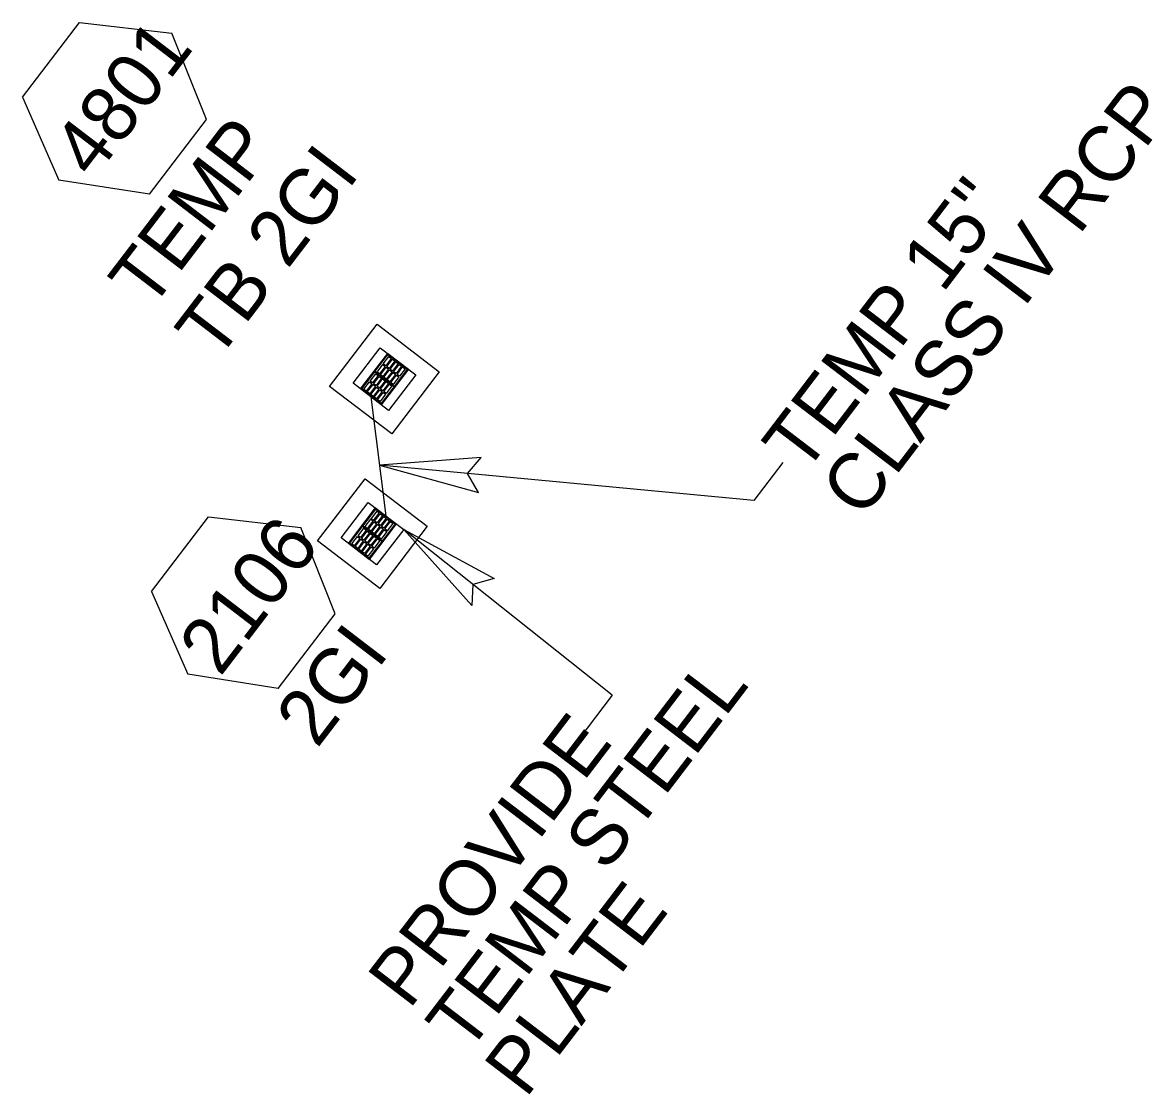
# Model space of a CAD drawing. Extents: x 2214419 to 2238519, y 983271 to 1015868.
# Drawn here: x 2224968.5 to 2225069.6, y 994806.5 to 994902.4 of the extents above; entities that cross this region are included whole.
import ezdxf

# ---------------------------------------------------------------- set-up
doc = ezdxf.new("R2010")
doc.units = 0
for name, color, linetype in [('Prop Drainage Structure Box Number Symbol CELL', 7, 'Continuous'), ('Prop Drainage Structure Drop Inlet Grate 2 Wide Slots and Sag Grates 840 22 CELL', 7, 'Continuous'), ('Prop Drainage Structure Drop Inlet Grate 2 Wide Slots and Sag Grates 840 22 Label', 7, 'Continuous'), ('Prop Drainage Structure Drop Inlet Grate 2 Wide Slots and Sag Grates 840 22 TB CELL', 7, 'Continuous'), ('Prop Drainage Structure Drop Inlet Grate 2 Wide Slots and Sag Grates 840 22 TB Label', 7, 'Continuous'), ('Prop Drainage Structure Pipe Alternate 15in', 7, 'Continuous'), ('Prop Drainage Structure Plot Symbol 20 Scale', 7, 'Continuous'), ('Prop Drainage Structure Plot Symbol 50 Scale', 7, 'Continuous'), ('Prop Plan Preparation Drainage Notes Label', 7, 'Continuous')]:
    doc.layers.add(name, color=color, linetype=linetype)

msp = doc.modelspace()

# ---------------------------------------------------------------- linework, layer by layer
at = {"layer": 'Prop Drainage Structure Box Number Symbol CELL'}
for p, q in [((2224968.47, 994895.68), (2224973.57, 994902.35)), ((2224973.57, 994902.35), (2224981.83, 994901.41)), ((2224984.91, 994893.68), (2224981.83, 994901.41)), ((2224968.47, 994895.68), (2224971.71, 994888.27)), ((2224979.81, 994887.01), (2224984.91, 994893.68)), ((2224979.81, 994887.01), (2224971.71, 994888.27)), ((2224980.01, 994851.47), (2224985.11, 994858.14)), ((2224985.11, 994858.14), (2224993.37, 994857.2)), ((2224996.45, 994849.47), (2224993.37, 994857.2)), ((2224980.01, 994851.47), (2224983.24, 994844.07)), ((2224991.35, 994842.8), (2224996.45, 994849.47)), ((2224991.35, 994842.8), (2224983.24, 994844.07))]:
    msp.add_line(p, q, dxfattribs=at)
at = {"layer": 'Prop Drainage Structure Drop Inlet Grate 2 Wide Slots and Sag Grates 840 22 CELL'}
for p, q in [((2225000.98, 994858.23), (2225000.98, 994858.23)), ((2224998.84, 994857.35), (2224998.84, 994857.35)), ((2224999.76, 994856.64), (2224999.76, 994856.64)), ((2225000.69, 994855.93), (2225000.69, 994855.93)), ((2224998.55, 994855.05), (2224998.55, 994855.05))]:
    msp.add_line(p, q, dxfattribs=at)
for points in [[(2224997.62, 994855.76), (2225000.05, 994858.94), (2225001.9, 994857.52), (2224999.48, 994854.34), (2224997.62, 994855.76)], [(2224997.71, 994855.77), (2225000.06, 994858.85), (2225001.82, 994857.51), (2224999.46, 994854.43), (2224997.71, 994855.77)], [(2224998.9, 994857.31), (2225000.06, 994858.84), (2225001.8, 994857.51), (2225000.64, 994855.98), (2224998.9, 994857.31)], [(2224999.32, 994857.1), (2224999.82, 994857.76), (2224999.61, 994857.93), (2224999.1, 994857.27), (2224999.32, 994857.1)], [(2224999.87, 994857.83), (2225000.38, 994858.49), (2225000.16, 994858.66), (2224999.66, 994857.99), (2224999.87, 994857.83)], [(2224999.96, 994857.76), (2225000.47, 994858.42), (2225000.68, 994858.26), (2225000.18, 994857.6), (2224999.96, 994857.76)], [(2225000.27, 994857.53), (2225000.78, 994858.19), (2225000.99, 994858.02), (2225000.48, 994857.36), (2225000.27, 994857.53)], [(2225000.58, 994857.29), (2225001.08, 994857.95), (2225001.3, 994857.79), (2225000.79, 994857.13), (2225000.58, 994857.29)], [(2224997.72, 994855.77), (2224998.89, 994857.3), (2225000.63, 994855.97), (2224999.46, 994854.45), (2224997.72, 994855.77)], [(2224998.48, 994856.45), (2224998.99, 994857.12), (2224999.2, 994856.95), (2224998.7, 994856.29), (2224998.48, 994856.45)], [(2224998.79, 994856.22), (2224999.29, 994856.88), (2224999.51, 994856.72), (2224999, 994856.06), (2224998.79, 994856.22)], [(2224999.41, 994857.03), (2224999.91, 994857.69), (2225000.13, 994857.53), (2224999.62, 994856.87), (2224999.41, 994857.03)], [(2224999.71, 994856.8), (2225000.22, 994857.46), (2225000.43, 994857.3), (2224999.93, 994856.63), (2224999.71, 994856.8)], [(2225000.02, 994856.56), (2225000.53, 994857.23), (2225000.74, 994857.06), (2225000.23, 994856.4), (2225000.02, 994856.56)], [(2225000.33, 994856.33), (2225000.83, 994856.99), (2225001.05, 994856.83), (2225000.54, 994856.16), (2225000.33, 994856.33)], [(2225000.88, 994857.06), (2225001.39, 994857.72), (2225001.6, 994857.56), (2225001.1, 994856.89), (2225000.88, 994857.06)], [(2224997.92, 994855.73), (2224998.43, 994856.39), (2224998.65, 994856.22), (2224998.14, 994855.56), (2224997.92, 994855.73)], [(2224998.23, 994855.49), (2224998.74, 994856.15), (2224998.95, 994855.99), (2224998.45, 994855.33), (2224998.23, 994855.49)], [(2224998.54, 994855.26), (2224999.04, 994855.92), (2224999.26, 994855.76), (2224998.75, 994855.09), (2224998.54, 994855.26)], [(2224999.09, 994855.99), (2224999.6, 994856.65), (2224999.81, 994856.48), (2224999.31, 994855.82), (2224999.09, 994855.99)], [(2224999.4, 994855.75), (2224999.91, 994856.41), (2225000.12, 994856.25), (2224999.61, 994855.59), (2224999.4, 994855.75)], [(2224999.71, 994855.52), (2225000.21, 994856.18), (2225000.43, 994856.02), (2224999.92, 994855.35), (2224999.71, 994855.52)], [(2224998.84, 994855.02), (2224999.35, 994855.69), (2224999.56, 994855.52), (2224999.06, 994854.86), (2224998.84, 994855.02)], [(2224999.15, 994854.79), (2224999.65, 994855.45), (2224999.87, 994855.29), (2224999.36, 994854.63), (2224999.15, 994854.79)]]:
    msp.add_lwpolyline(points, dxfattribs=at)
at = {"layer": 'Prop Drainage Structure Drop Inlet Grate 2 Wide Slots and Sag Grates 840 22 TB CELL'}
for p, q in [((2225002.06, 994872.06), (2225002.06, 994872.06)), ((2224999.92, 994871.18), (2224999.92, 994871.18)), ((2225000.85, 994870.47), (2225000.85, 994870.47)), ((2225001.78, 994869.76), (2225001.78, 994869.76)), ((2224999.63, 994868.88), (2224999.63, 994868.88))]:
    msp.add_line(p, q, dxfattribs=at)
for points in [[(2225002.99, 994871.35), (2225000.56, 994868.17), (2224998.71, 994869.59), (2225001.14, 994872.77), (2225002.99, 994871.35)], [(2225002.9, 994871.34), (2225000.55, 994868.26), (2224998.79, 994869.6), (2225001.15, 994872.68), (2225002.9, 994871.34), (2225002.9, 994871.34)], [(2225002.89, 994871.34), (2225001.72, 994869.81), (2224999.99, 994871.14), (2225001.15, 994872.67), (2225002.89, 994871.34)], [(2225001.46, 994872.32), (2225000.96, 994871.66), (2225000.74, 994871.82), (2225001.25, 994872.49), (2225001.46, 994872.32)], [(2225001.77, 994872.09), (2225001.26, 994871.42), (2225001.05, 994871.59), (2225001.55, 994872.25), (2225001.77, 994872.09)], [(2225001.71, 994869.8), (2225000.55, 994868.27), (2224998.81, 994869.6), (2224999.97, 994871.13), (2225001.71, 994869.8)], [(2225000.91, 994871.59), (2225000.4, 994870.93), (2225000.19, 994871.09), (2225000.69, 994871.76), (2225000.91, 994871.59)], [(2225001.21, 994871.36), (2225000.71, 994870.7), (2225000.49, 994870.86), (2225001, 994871.52), (2225001.21, 994871.36)], [(2225001.52, 994871.12), (2225001.01, 994870.46), (2225000.8, 994870.63), (2225001.3, 994871.29), (2225001.52, 994871.12)], [(2225001.83, 994870.89), (2225001.32, 994870.23), (2225001.1, 994870.39), (2225001.61, 994871.05), (2225001.83, 994870.89)], [(2225002.08, 994871.85), (2225001.57, 994871.19), (2225001.35, 994871.35), (2225001.86, 994872.02), (2225002.08, 994871.85)], [(2225002.38, 994871.62), (2225001.88, 994870.96), (2225001.66, 994871.12), (2225002.17, 994871.78), (2225002.38, 994871.62)], [(2225002.69, 994871.38), (2225002.18, 994870.72), (2225001.97, 994870.89), (2225002.47, 994871.55), (2225002.69, 994871.38)], [(2224999.73, 994870.05), (2224999.22, 994869.39), (2224999.01, 994869.56), (2224999.51, 994870.22), (2224999.73, 994870.05)], [(2225000.29, 994870.78), (2224999.78, 994870.12), (2224999.57, 994870.28), (2225000.07, 994870.95), (2225000.29, 994870.78)], [(2225000.59, 994870.55), (2225000.09, 994869.89), (2224999.87, 994870.05), (2225000.38, 994870.71), (2225000.59, 994870.55)], [(2225000.9, 994870.31), (2225000.39, 994869.65), (2225000.18, 994869.82), (2225000.68, 994870.48), (2225000.9, 994870.31)], [(2225001.21, 994870.08), (2225000.7, 994869.42), (2225000.48, 994869.58), (2225000.99, 994870.24), (2225001.21, 994870.08)], [(2225002.13, 994870.66), (2225001.63, 994869.99), (2225001.41, 994870.16), (2225001.92, 994870.82), (2225002.13, 994870.66)], [(2225000.04, 994869.82), (2224999.53, 994869.16), (2224999.31, 994869.32), (2224999.82, 994869.98), (2225000.04, 994869.82)], [(2225000.34, 994869.58), (2224999.84, 994868.92), (2224999.62, 994869.09), (2225000.13, 994869.75), (2225000.34, 994869.58)], [(2225000.65, 994869.35), (2225000.14, 994868.69), (2224999.93, 994868.85), (2225000.43, 994869.52), (2225000.65, 994869.35)], [(2225000.95, 994869.12), (2225000.45, 994868.45), (2225000.23, 994868.62), (2225000.74, 994869.28), (2225000.95, 994869.12)], [(2225001.51, 994869.85), (2225001.01, 994869.18), (2225000.79, 994869.35), (2225001.3, 994870.01), (2225001.51, 994869.85)]]:
    msp.add_lwpolyline(points, dxfattribs=at)
at = {"layer": 'Prop Drainage Structure Pipe Alternate 15in'}
msp.add_line((2224999.63, 994868.88), (2225000.98, 994858.23), dxfattribs=at)
at = {"layer": 'Prop Drainage Structure Plot Symbol 20 Scale'}
for points in [[(2225003.65, 994870.84), (2225001.22, 994867.67), (2224998.04, 994870.1), (2225000.47, 994873.27)], [(2224996.96, 994856.27), (2224999.39, 994859.44), (2225002.57, 994857.02), (2225000.14, 994853.84)]]:
    msp.add_lwpolyline(points, close=True, dxfattribs=at)
at = {"layer": 'Prop Drainage Structure Plot Symbol 50 Scale'}
for points in [[(2225005.75, 994871.13), (2225001.5, 994865.56), (2224995.94, 994869.81), (2225000.19, 994875.38)], [(2224994.86, 994855.99), (2224999.11, 994861.55), (2225004.67, 994857.3), (2225000.42, 994851.73)]]:
    msp.add_lwpolyline(points, close=True, dxfattribs=at)
at = {"layer": 'Prop Plan Preparation Drainage Notes Label'}
for p, q in [((2225036.49, 994863.01), (2225033.88, 994859.6)), ((2225033.88, 994859.6), (2225000.41, 994862.76)), ((2225021.23, 994842.2), (2225002.57, 994857.02)), ((2225021.23, 994842.2), (2225017.49, 994837.29))]:
    msp.add_line(p, q, dxfattribs=at)
for points in [[(2225009.51, 994863.46), (2225000.41, 994862.76), (2225009.27, 994860.32), (2225008.27, 994862.02)], [(2225008.65, 994850.21), (2225002.57, 994857.02), (2225010.65, 994852.64), (2225008.75, 994852.1)]]:
    msp.add_lwpolyline(points, close=True, dxfattribs=at)

# ---------------------------------------------------------------- texts
at = {"layer": 'Prop Drainage Structure Box Number Symbol CELL'}
for s, rotation, p in [('4801', 52.6076, (2224974.81, 994888.24)), ('2106', 52.6073, (2224986.14, 994843.77))]:
    msp.add_text(s, height=5, rotation=rotation, dxfattribs=at).set_placement(p)
at = {"layer": 'Prop Drainage Structure Drop Inlet Grate 2 Wide Slots and Sag Grates 840 22 Label'}
msp.add_text('2GI', height=5, rotation=52.6073, dxfattribs=at).set_placement((2224994.81, 994837.36))
at = {"layer": 'Prop Drainage Structure Drop Inlet Grate 2 Wide Slots and Sag Grates 840 22 TB Label'}
for s, p in [('TEMP', (2224979.9, 994876.53)), ('TB 2GI', (2224985.85, 994871.97))]:
    msp.add_text(s, height=5, rotation=52.6076, dxfattribs=at).set_placement(p)
at = {"layer": 'Prop Plan Preparation Drainage Notes Label'}
for s, rotation, p in [('CLASS IV RCP', 52.664, (2225043.6, 994857.85)), ('TEMP 15"', 52.664, (2225038.39, 994861.83)), ('TEMP STEEL', 52.6215, (2225008.28, 994810.03)), ('PROVIDE', 52.6215, (2225003.07, 994814.01)), ('PLATE', 52.6215, (2225013.49, 994806.06))]:
    msp.add_text(s, height=5, rotation=rotation, dxfattribs=at).set_placement(p)

doc.saveas('drawing.dxf')
